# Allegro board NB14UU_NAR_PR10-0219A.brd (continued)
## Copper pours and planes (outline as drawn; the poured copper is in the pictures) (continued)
INT_SPK_L+ on TOP (solid shape): 281.62,53.86 283.39,53.86 283.43,53.83 283.43,53.68 283.37,53.62 281.35,53.62 281.21,53.48 279.46,53.48 279.46,54.11 279.52,54.18 281.3,54.18
INT_SPK_L+ on IN1 (solid shape): 290.89,38.49 290.89,37.28 290.7,37.09 290,37.09 289.75,37.35 289.75,38.49 289.87,38.62 290.76,38.62
INT_SPK_L+ on IN1 (solid shape): 281.24,54.18 281.24,53.6 281.11,53.48 279.46,53.48 278.38,52.4 277.55,52.4 277.24,52.72 277.24,53.16 277.49,53.41 278.38,53.41 279.2,54.24 281.17,54.24
INT_SPK_L- on TOP (solid shape): 289.24,38.55 289.24,37.67 289.05,37.48 288.29,37.48 288.03,37.73 288.03,38.49 288.16,38.62 289.17,38.62
INT_SPK_L- on TOP (solid shape): 283.43,53.42 283.43,53.29 283.38,53.24 281.79,53.24 281.12,52.58 279.54,52.58 279.46,52.65 279.46,53.19 279.52,53.25 281.17,53.25 281.37,53.45 283.4,53.45
INT_SPK_L- on IN1 (solid shape): 289.24,38.43 289.24,37.79 288.48,37.03 288.16,37.03 287.71,37.48 287.71,37.79 288.03,38.11 288.03,38.36 288.29,38.62 289.05,38.62
INT_SPK_L- on IN1 (solid shape): 281.24,53.1 281.24,52.72 281.17,52.65 279.97,52.65 277.93,50.62 277.93,49.92 277.74,49.73 277.05,49.73 276.92,49.86 276.92,50.62 279.52,53.22 281.11,53.22
INT_SPK_R+ on TOP (solid shape): 287.33,38.49 287.33,37.67 287.14,37.48 286.38,37.48 286.19,37.67 286.19,38.49 286.32,38.62 287.21,38.62
INT_SPK_R+ on TOP (solid shape): 283.44,52.62 283.44,52.47 283.4,52.44 282.31,52.44 281.62,51.75 281.62,51.47 280.78,50.63 279.64,50.63 279.46,50.81 279.46,51.38 279.52,51.45 281.02,51.45 281.38,51.81 281.38,52 282.04,52.66 283.39,52.66
INT_SPK_R+ on IN1 (solid shape): 281.24,51.32 281.24,49.92 281.11,49.79 280.35,49.79 280.22,49.92 280.22,50.94 280.09,51.06 280.09,51.32 280.22,51.45 281.11,51.45
INT_SPK_R+ on IN1 (solid shape): 287.33,39.7 287.33,38.3 287.14,38.11 286.38,38.11 286.19,38.3 286.19,39.32 285.68,39.82 285.68,40.14 286,40.46 286.57,40.46
INT_SPK_R- on TOP (solid shape): 285.43,38.49 285.43,37.6 285.3,37.48 284.48,37.48 284.28,37.67 284.28,38.49 284.41,38.62 285.3,38.62
INT_SPK_R- on TOP (solid shape): 283.43,53.01 283.43,52.88 283.37,52.82 281.99,52.82 281.23,52.06 281.23,51.85 281.09,51.71 279.51,51.71 279.46,51.77 279.46,52.33 279.52,52.4 281.16,52.4 281.81,53.05 283.4,53.05
INT_SPK_R- on IN1 (solid shape): 281.24,52.14 281.24,51.95 281.05,51.76 280.22,51.76 279.71,51.25 279.71,49.92 279.59,49.79 278.82,49.79 278.7,49.92 278.7,51.13 279.84,52.27 281.11,52.27
INT_SPK_R- on IN1 (solid shape): 285.43,39 285.43,38.24 285.3,38.11 284.48,38.11 283.65,38.94 283.65,39.57 284.09,40.02 284.41,40.02
INT_SPKR_L+ on TOP (solid shape): 291.27,36.65 291.27,35.06 292.1,34.24 292.1,33.92 291.71,33.54 291.27,33.54 290.13,34.68 290.13,37.03 290.19,37.09 290.83,37.09
INT_SPKR_L+ on TOP (solid shape): 294.32,32.08 294.32,29.86 294.13,29.66 293.56,29.66 293.43,29.79 293.43,31.51 293.17,31.76 293.17,32.08 293.43,32.33 294.06,32.33
INT_SPKR_L+ on BOTTOM (solid shape): 294.25,30.55 294.25,27.38 294.06,27.19 293.49,27.19 293.37,27.32 293.37,30.62 293.56,30.81 294,30.81
INT_SPKR_L- on TOP (solid shape): 289.3,36.9 289.3,34.49 289.11,34.3 289.11,33.03 288.86,32.78 288.22,32.78 288.09,32.9 288.09,36.65 288.54,37.09 289.11,37.09
INT_SPKR_L- on TOP (solid shape): 292.86,31.32 292.86,29.79 292.73,29.66 292.29,29.66 291.84,30.11 291.84,30.49 291.52,30.81 291.14,30.81 291.02,30.93 291.02,31.51 291.33,31.82 292.35,31.82
INT_SPKR_L- on BOTTOM (solid shape): 292.98,30.55 292.98,27.38 292.79,27.19 292.35,27.19 292.16,27.38 292.16,30.55 292.41,30.81 292.73,30.81
INT_SPKR_R+ on TOP (solid shape): 287.46,32.08 287.46,31.25 287.78,30.93 287.78,30.62 287.59,30.43 286.91,30.43 286.33,31.01 286.33,32.03 286.57,32.27 287.27,32.27
INT_SPKR_R+ on TOP (solid shape): 287.4,36.8 287.4,34.08 287.52,33.97 287.52,33.38 287.47,33.34 286.44,33.34 286.44,33.34 286.37,33.55 286.23,33.73 286.23,36.97 286.36,37.1 287.11,37.1
INT_SPKR_R+ on BOTTOM (solid shape): 287.29,31.31 287.59,31.31 287.82,31.24 288.04,31.32 290.76,31.32 291.71,30.36 291.71,27.38 291.52,27.19 291.08,27.19 290.89,27.38 290.89,29.41 290.13,30.17 288.66,30.17 288.41,30.28 288.16,30.17 287.33,30.17 286.7,30.81 286.7,31.19 286.82,31.32 287.29,31.32
INT_SPKR_R- on TOP (solid shape): 285.37,36.89 285.37,33.72 285.28,33.62 285.22,33.49 285.12,33.4 284.26,33.4 284.19,33.47 284.19,36.98 284.3,37.09 285.17,37.09
INT_SPKR_R- on TOP (solid shape): 285.17,31.95 285.17,31.44 285.94,30.67 285.94,30.27 285.77,30.1 284.99,30.1 284.16,30.93 284.16,31.95 284.41,32.2 284.92,32.2
INT_SPKR_R- on BOTTOM (solid shape): 287.47,29.09 288.16,29.09 288.41,28.98 288.67,29.09 290.23,29.09 290.47,28.85 290.47,27.43 290.22,27.18 289.76,27.18 289.62,27.32 289.62,27.89 289.43,28.08 286.76,28.08 284.67,30.17 284.67,30.57 285.17,31.08 285.48,31.08
LDO_3V on BOTTOM (solid shape): 207.77,37.22 207.7,37.16 206.31,37.16 206.18,37.03 206.18,34.62 206.05,34.49 205.35,34.49 205.23,34.62 205.23,35.19 205.48,35.44 205.48,37.72 207.77,37.72
LG1_CHG on BOTTOM (solid shape): 86.09,44.63 86.75,44.63 87.03,44.35 87.03,44.09 86.88,43.94 85.74,43.94 85.63,44.04 85.63,44.8 85.68,44.85 85.86,44.85
LG1_CHG on BOTTOM (solid shape): 105.02,34.55 105.02,32.59 104.77,32.33 103.88,32.33 103.69,32.52 103.69,33.35 103.25,33.79 103.25,34.55 103.31,34.62 104.96,34.62
LG1_CHG on IN1 (solid shape): 104.9,33.03 104.9,32.52 104.71,32.33 102.8,32.33 102.55,32.59 102.55,33.03 102.87,33.35 104.58,33.35
LG1_CHG on IN1: 86.43,43.86 86.12,43.86 85.93,44.05 85.93,44.44 86.12,44.63 87.07,44.63 88.21,43.48 88.21,42.82 88.17,42.78 87.21,42.78 87.16,42.84 87.16,43.14
LG2_CHG on BOTTOM (solid shape): 122.23,40.14 122.23,39.57 122.11,39.44 120.52,39.44 120.2,39.13 119.95,39.13 119.76,39.32 119.76,40.08 120.01,40.33 122.04,40.33
LG2_CHG on BOTTOM (solid shape): 87.98,45.16 87.98,44.85 87.88,44.75 87.58,44.75 86.97,45.36 85.98,45.36 85.93,45.41 85.93,45.51 85.98,45.57 86.84,45.57 86.89,45.62 87.53,45.62
LG2_CHG on IN1 (solid shape): 120.33,40.14 120.33,39.25 120.2,39.13 118.8,39.13 118.61,39.32 118.61,39.95 118.93,40.27 120.2,40.27
LG2_CHG on IN1: 87.01,45.35 87.01,45.58 87.13,45.71 87.7,45.71 87.89,45.51 88.64,45.51 89.22,44.94 89.22,44.72 88.61,44.11 88.47,44.11 87.83,44.74 87.61,44.74
LG_SA on TOP (solid shape): 176.94,135.19 176.94,134.44 177.11,134.27 177.11,133.78 177.05,133.72 176.16,133.72 176.11,133.77 176.11,135.2 176.16,135.25 176.89,135.25
LG_SA on TOP (solid shape): 185.87,133.79 185.87,133.32 185.69,133.13 184.25,133.13 184.02,132.9 183.07,132.9 182.97,132.99 182.97,133.71 183.03,133.77 183.95,133.77 184.06,133.88 185.78,133.88
LG_SA on IN3 (solid shape): 176.96,135.08 176.96,134.11 177.19,133.89 182.63,133.89 182.77,133.75 185.56,133.75 185.73,133.59 185.73,131.87 185.64,131.79 183.53,131.79 182.49,132.83 176.44,132.83 176.1,133.17 176.1,135.11 176.18,135.19 176.85,135.19
LX1_CHG on BOTTOM (solid shape): 99.5,35.89 99.5,35.25 99.44,35.19 98.93,35.19 98.74,35 98.36,35 98.23,35.13 98.23,36.01 98.36,36.14 99.25,36.14
LX1_CHG on BOTTOM (solid shape): 110.36,39.82 110.36,33.98 109.98,33.6 106.87,33.6 105.21,35.25 104.39,35.25 104.39,38.43 105.66,39.7 105.66,40.46 105.72,40.52 109.66,40.52
LX1_CHG on BOTTOM (solid shape): 85.44,44.83 85.44,44.04 86.5,42.99 86.5,41.64 85.61,41.64 85.55,41.7 85.55,43.04 85.23,43.36 85.23,44.82 85.27,44.85 85.42,44.85
LX1_CHG on IN3 (solid shape): 105.98,35.95 105.98,35.13 105.79,34.94 105.47,34.94 105.09,34.55 104.77,34.55 104.33,35 104.33,35.25 105.15,36.08 105.85,36.08
LX1_CHG on IN3 (solid shape): 99.75,35.06 99.75,34.74 99.63,34.62 98.8,34.62 98.29,35.13 97.34,35.13 97.15,35.32 97.15,36.01 97.28,36.14 98.67,36.14
LX1_CHG on IN3: 85.35,43.23 85.35,43.61 85.48,43.74 87.39,43.74 87.39,42.72 85.86,42.72
LX1_IA on TOP (solid shape): 118.61,106.31 118.61,105.1 118.36,104.85 116.96,104.85 116.9,104.91 116.9,106.56 116.96,106.63 118.3,106.63
LX1_IA on BOTTOM (solid shape): 115.76,108.09 115.76,107.07 116.58,107.07 116.58,108.02 116.77,108.21 118.74,108.21 119.25,107.71 119.25,102.5 119.06,102.31 118.23,102.31 118.17,102.37 118.17,103.52 117.91,103.77 114.17,103.77 113.79,104.15 113.79,107.9 114.17,108.28 115.57,108.28
LX2_CHG on BOTTOM (solid shape): 127.19,39.06 127.19,38.17 127.06,38.05 125.98,38.05 125.92,38.11 125.92,38.75 125.98,38.81 126.36,38.81 126.74,39.19 127.06,39.19
LX2_CHG on BOTTOM (solid shape): 119.44,42.75 119.44,39.19 119.76,38.87 121.03,38.87 121.09,38.81 121.09,34.49 120.58,33.98 115.25,33.98 114.75,34.49 114.75,41.86 115.88,43 119.18,43
LX2_CHG on BOTTOM (solid shape): 89.48,46.26 89.48,45.45 89.16,45.13 88.26,45.13 87.65,45.74 85.98,45.74 85.93,45.79 85.93,45.92 85.98,45.97 88.16,45.97 88.28,46.09 88.72,46.09 89.03,46.39 89.35,46.39
LX2_CHG on IN3 (solid shape): 90.67,46.63 90.67,45.62 90.28,45.23 89.07,45.23 88.94,45.36 88.94,46.5 89.15,46.71 90.6,46.71
LX2_CHG on IN3 (solid shape): 126.74,40.52 126.74,39.51 127.25,39 127.25,38.24 127.06,38.05 126.3,38.05 125.73,38.62 125.73,40.46 126.11,40.84 126.42,40.84
LX2_CHG on IN3 (solid shape): 121.47,39.38 121.47,38.94 120.14,37.6 118.87,37.6 118.61,37.86 118.61,38.49 118.87,38.75 120.07,38.75 120.45,39.13 120.45,39.38 120.65,39.57 121.28,39.57
LX2_IA on TOP (solid shape): 101.72,111.71 101.53,111.52 100.26,111.52 100.07,111.71 100.07,113.29 101.72,113.29
LX2_IA on BOTTOM (solid shape): 102.48,115.96 102.48,114.5 102.29,114.31 101.28,114.31 101.28,113.48 102.23,113.48 102.36,113.36 102.36,112.62 105.98,109 105.98,107.82 105.42,107.26 104.26,107.26 104.26,108.47 104.01,108.72 99.74,108.72 98.51,109.95 98.51,113.93 98.54,114.14 98.51,114.35 98.51,115.35 99.31,116.15 102.29,116.15
LX_1.05VALWP on TOP (solid shape): 234.41,129.88 234.41,128.64 234.27,128.5 233.73,128.5 233.61,128.62 233.61,129.65 233.55,129.72 233.55,129.91 233.61,129.97 234.31,129.97
LX_1.05VALWP on TOP (solid shape): 229.22,133.24 229.22,130.8 229.59,130.43 231.21,130.43 231.33,130.31 231.33,129.8 231.01,129.49 231.01,128.66 230.5,128.15 230.5,127.2 230.37,127.07 227.9,127.07 226.65,128.32 226.65,133.46 226.69,133.5 228.96,133.5
LX_1.05VALWP on BOTTOM (solid shape): 234.12,129.45 234.12,128.63 234,128.51 230.52,128.51 229.9,127.9 228.66,127.9 228.66,129.55 228.69,129.58 233.98,129.58
LX_1.8VALW on BOTTOM (solid shape): 198.5,114.37 198.69,114.18 201.36,114.18 201.8,113.75 201.8,113.23 201.61,113.04 197.92,113.04 197.86,113.1 197.86,115.33 198.5,115.33
LX_1V_PRIM_CORE on TOP (solid shape): 207.83,131.14 207.83,130.5 207.77,130.44 206.97,130.44 206.61,130.07 206.61,129.28 206.08,128.75 204.89,128.75 204.87,128.72 203.51,128.72 203.39,128.85 203.39,130.12 204.47,131.2 207.77,131.2
LX_1V_PRIM_CORE on BOTTOM (solid shape): 205.16,131.01 205.16,130.12 205.04,129.99 203.88,129.99 203.75,130.12 203.75,131.02 203.86,131.13 203.95,131.13 203.96,131.14 205.04,131.14
LX_1VS_VCCIO on TOP: 106.83,75.69 106.83,75.08 106.9,75.01 110.55,75.01 110.93,75.38 110.93,76.78 110.8,76.91 110.17,76.91 109.79,77.29 109.79,77.8 109.66,77.92 108.14,77.92 107.88,77.67 107.88,75.89 107.75,75.76 106.9,75.76
LX_3V on TOP (solid shape): 206.19,35.28 206.19,32.09 205.95,31.85 204.87,31.85 204.65,32.07 204.65,35.29 204.79,35.43 206.04,35.43
LX_3V on BOTTOM (solid shape): 203.03,33.34 203.03,33.21 202.81,32.99 202.81,32.54 202.32,32.04 202.01,32.04 201.93,32.13 201.93,33.11 202.22,33.4 202.97,33.4
LX_3V on BOTTOM (solid shape): 210.37,34.36 210.37,31.19 209.61,30.43 205.54,30.43 205.42,30.55 205.42,33.06 205.27,33.21 205.27,33.79 205.33,33.86 206.94,33.86 207.26,34.17 207.26,34.81 207.32,34.87 209.86,34.87
LX_3V on IN2 (solid shape): 202.75,32.9 205.48,32.9 205.61,33.03 205.93,33.03 206.05,32.9 206.05,32.08 205.86,31.89 202.12,31.89 201.93,32.08 201.93,32.65 202.31,33.03 202.62,33.03
LX_5V on BOTTOM (solid shape): 87.69,77.8 87.69,76.53 85.78,74.62 81.82,74.62 80.26,73.06 79.7,73.06 79.63,73.14 79.63,77.23 80.32,77.92 87.56,77.92
LX_5V on IN3 (solid shape): 81.47,74.75 81.47,74.5 81.15,74.18 81.15,69.73 80.96,69.54 80.51,69.54 80.32,69.73 80.32,74.75 80.45,74.88 81.34,74.88
LX_5V on BOTTOM: 80.15,70.85 80.79,70.85 80.96,70.69 80.96,69.67 80.83,69.54 80.32,69.54 80.08,69.79 80.08,70.78
LX_DDR on TOP (solid shape): 91.95,63.4 91.95,62.06 91.74,61.86 89.85,61.86 89.6,62.11 89.6,63.45 89.73,63.57 91.78,63.57
LX_DDR on BOTTOM (solid shape): 92.2,59.07 91.18,58.05 87.37,58.05 87.18,58.24 87.18,60.51 87.03,60.67 85.72,60.67 85.61,60.78 85.61,61.49 85.71,61.59 87.17,61.59 87.24,61.67 88.32,61.67 90.86,64.21 90.86,65.86 92.2,65.86
LX_GT on TOP (solid shape): 111.76,86.37 111.76,84.85 111.56,84.66 110.23,84.66 109.98,84.91 109.98,86.37 110.04,86.43 111.69,86.43
LX_GT on BOTTOM (solid shape): 113.09,89.8 113.09,88.34 112.96,88.21 111.88,88.21 111.88,87.32 112.9,87.32 113.03,87.2 113.03,85.1 112.39,84.47 107.69,84.47 107.12,85.04 107.12,85.99 108.39,85.99 108.58,86.18 108.58,89.93 108.71,90.05 112.83,90.05
LX_SA on TOP (solid shape): 176.04,133.55 179.19,133.55 179.76,134.12 179.76,134.19 179.83,134.25 181.35,134.25 181.8,133.8 181.8,132.98 181.73,132.92 181.61,132.92 180.97,133.55 179.89,133.55 179.13,132.79 179.13,132.53 179,132.41 176.46,132.41 176.21,132.15 176.21,131.49 175.99,131.26 174.57,131.26 174.08,130.77 173.09,130.77 172.91,130.96 172.91,132.28 173.03,132.41 173.99,132.41 173.99,133.23 173.03,133.23 172.98,133.29 172.98,134.26 173.11,134.39 175.2,134.39
LX_SA on BOTTOM (solid shape): 175.28,132.78 175.28,131.09 175.08,130.88 173.14,130.88 173,131.03 173,132.52 173.46,132.99 175.07,132.99
RING2 on TOP (solid shape): 290.83,52.53 290.83,52.14 290.7,52.01 289.35,52.01 288.98,52.38 288.84,52.38 288.81,52.41 287.73,52.41 287.66,52.47 287.66,52.6 287.73,52.66 290.7,52.66
RING2 on BOTTOM (solid shape): 300.51,34.55 300.51,33.94 300.17,33.6 299.65,33.6 299.53,33.59 299.42,33.56 299.41,33.56 297.28,33.56 296.89,33.95 296.89,34.72 296.94,34.77 300.29,34.77
RING2 on IN1 (solid shape): 292.03,52.21 292.03,51.45 291.78,51.19 289.75,51.19 289.17,51.76 289.17,52.4 289.3,52.52 291.71,52.52
RING2 on IN1 (solid shape): 300.53,35.52 300.53,33.72 300.4,33.59 299.41,33.59 299.19,33.81 299.19,35.43 299.55,35.79 300.27,35.79
RING2_R on BOTTOM (solid shape): 303.51,37.26 303.51,35.39 303.2,35.08 302.43,35.08 302.27,35.25 302.27,35.92 302.08,36.11 301.84,36.11 300.79,35.05 297.05,35.05 296.89,35.21 296.89,36.39 296.97,36.47 300.19,36.47 301.27,37.55 303.22,37.55
SLEEVE on TOP (solid shape): 290.83,53.29 290.83,52.97 290.7,52.84 289.11,52.84 289.11,52.84 287.7,52.84 287.7,53.04 288.8,53.04 289.17,53.41 290.7,53.41
SLEEVE on BOTTOM (solid shape): 296.8,38.68 296.8,38.2 297.01,37.99 297.01,37.66 296.8,37.45 296.8,36.66 296.61,36.48 295.97,36.48 295.91,36.54 295.91,38.78 295.94,38.81 296.66,38.81
SLEEVE on IN3 (solid shape): 292.1,53.67 292.1,52.91 291.9,52.72 289.43,52.72 289.17,52.97 289.17,53.73 289.43,53.99 291.78,53.99
SLEEVE on IN3 (solid shape): 297.05,39.19 297.05,37.28 296.92,37.16 296.1,37.16 295.78,37.48 295.78,39.19 296.03,39.44 296.79,39.44
SLEEVE_R on BOTTOM (solid shape): 301.3,39.89 303.33,39.89 303.53,39.7 303.53,38.62 303.07,38.16 301.39,38.16 301.01,38.55 299.09,38.55 298.56,39.07 296.01,39.07 295.91,39.18 295.91,40.23 296.07,40.4 300.79,40.4
SLEEVE_R on IN3 (solid shape): 303.46,39.72 303.46,39.14 303.26,38.94 302.42,38.94 302.24,39.11 302.24,39.72 302.4,39.88 303.31,39.88
SNUB1_IA on TOP (solid shape): 115.25,106.56 115.25,104.91 113.6,104.91 113.22,105.29 113.22,106.44 113.41,106.63 115.18,106.63
SNUB2_IA on TOP (solid shape): 101.72,109.61 99.28,109.61 99.12,109.77 99.12,110.5 99.25,110.63 101.72,110.63
SNUB_1.05VALWP on BOTTOM (solid shape): 227.45,128.09 227.26,127.9 225.99,127.9 225.99,130.19 226.63,130.82 227.45,130.82
SNUB_1.8VALW on BOTTOM (solid shape): 200.74,115.24 200.74,114.58 200.58,114.42 199.17,114.42 199.13,114.46 199.13,115.35 199.17,115.39 200.59,115.39
SNUB_1VS_VCCIO on TOP: 108.77,79.32 110.68,79.32 110.8,79.19 110.8,78.69 110.55,78.43 108.77,78.43 108.64,78.56 108.64,79.19
SNUB_3V on TOP (solid shape): 203.45,33.67 202.43,33.67 202.43,34.17 202.18,34.43 201.65,34.43 201.48,34.59 201.48,35.32 203.45,35.32
SNUB_5V on BOTTOM (solid shape): 87.72,81.2 87.72,79.35 87.56,79.19 86.04,79.19 85.78,79.45 85.78,81.48 85.91,81.61 87.31,81.61
SNUB_DDR on TOP (solid shape): 91.18,67.19 91.18,66.43 91.37,66.24 91.4,66.24 91.41,66.21 91.44,66.17 91.47,66.13 91.47,65.11 91.37,65.01 89.84,65.01 89.68,65.18 89.68,66.35 90.58,67.26 91.12,67.26
SNUB_GT on TOP (solid shape): 111.76,89.86 111.76,88.08 111.69,88.02 110.04,88.02 109.98,88.08 109.98,89.04 110.49,89.55 110.49,90.31 110.55,90.37 111.25,90.37
UG1_CHG on BOTTOM (solid shape): 85.09,44.78 85.09,42.71 84.97,42.59 84.73,42.59 84.6,42.72 84.6,43.51 84.83,43.74 84.83,44.8 84.88,44.85 85.01,44.85
UG1_CHG on BOTTOM (solid shape): 98.74,34.68 99.44,34.68 99.5,34.62 99.5,33.98 99.44,33.92 98.86,33.92 98.61,33.67 98.17,33.67 97.98,33.86 97.98,34.68 98.1,34.81 98.61,34.81
UG1_CHG on IN3 (solid shape): 98.48,34.62 98.48,33.79 98.36,33.67 97.47,33.67 97.21,33.92 97.21,34.68 97.34,34.81 98.29,34.81
UG1_CHG on IN3: 84.34,42.15 84.34,43.55 84.47,43.67 85.04,43.67 85.1,43.61 85.1,43.17 85.74,42.53 85.99,42.53 85.99,41.51 84.97,41.51
UG2_CHG on BOTTOM (solid shape): 127.57,40.4 127.57,39.63 127.38,39.44 125.92,39.44 125.92,40.08 125.98,40.14 126.61,40.14 127.06,40.59 127.38,40.59
UG2_CHG on BOTTOM (solid shape): 88.08,46.61 88.08,46.2 87.98,46.1 86.92,46.1 86.87,46.15 85.98,46.15 85.93,46.2 85.93,46.33 85.98,46.38 87.02,46.38 87.2,46.56 87.6,46.56 87.75,46.71 87.98,46.71
UG2_CHG on IN3 (solid shape): 88.91,47.55 88.91,46.98 87.96,46.02 87.2,46.02 87.01,46.21 87.01,46.47 88.15,47.61 88.85,47.61
UG2_CHG on IN3 (solid shape): 127.76,41.35 127.76,39.63 127.57,39.44 127.19,39.44 126.93,39.7 126.93,40.65 126.55,41.03 126.55,41.48 126.8,41.73 127.38,41.73
UG_SA on TOP (solid shape): 177.13,131.39 177.13,130.48 177,130.36 176.09,130.36 176.01,130.43 176.01,130.75 176.74,131.48 177.04,131.48
UG_SA on TOP (solid shape): 181.47,132.14 181.47,131.67 181.58,131.57 181.72,131.57 181.77,131.52 181.77,130.81 181.66,130.7 180.99,130.7 180.71,130.98 180.71,131.97 180.98,132.24 181.37,132.24
UG_SA on IN1 (solid shape): 181.38,132.13 181.38,131.19 181.27,131.08 177.72,131.08 177,130.36 176.09,130.36 176.01,130.43 176.01,131.07 177.23,132.28 181.23,132.28
VOUT_1.2V_RUN on TOP: 285.87,97.14 286.23,96.78 288.38,96.78 288.4,96.76 288.4,96.22 288.18,96 288.18,95.18 288.17,95.17 287.63,95.17 287.62,95.15 287.62,94.71 287.63,94.71 288.17,94.71 288.18,94.7 288.18,94.36 288.05,94.23 285.96,94.23 285.96,94.24 285.46,94.24 285.19,94.51 285.19,96.38 284.82,96.75 284.82,97.01 284.95,97.14
VOUT_2.5V_MEM on TOP (solid shape): 242.23,58.43 242.23,56.59 242.68,56.13 244.11,56.13 244.17,56.07 244.17,55.61 244.14,55.59 242.34,55.59 242.15,55.78 241.64,55.78 241.64,56.35 241.13,56.35 241.13,55.78 240.21,55.78 240,56 240,58.11 240.18,58.29 241.58,58.29 241.85,58.56 242.1,58.56
N43975 on TOP: 252.05,33.98 253.15,33.98 253.29,33.84 253.29,32.21 253.02,31.94 252.3,31.94 251.97,32.27 251.97,33.91
N16783222 on BOTTOM: 76.13,74.37 78.8,74.37 78.98,74.18 78.98,73.14 78.91,73.06 78.33,73.06 78.16,73.23 77.15,73.23 76.77,73.61 76.13,73.61 76,73.73 76,74.24
N17370862 on BOTTOM (solid shape): 77.91,113.36 77.91,112.85 77.66,112.6 77.66,109.8 77.53,109.67 77.02,109.67 76.89,109.8 76.89,112.72 76.77,112.85 75.62,112.85 75.31,112.53 75.31,111.77 74.99,111.45 74.48,111.45 74.1,111.83 74.1,113.23 74.48,113.61 77.66,113.61
N17371029 on BOTTOM (solid shape): 77.02,119.96 77.4,119.96 77.57,119.8 77.57,119.37 77.44,119.24 74.84,119.24 74.73,119.34 74.73,120.05 75.28,120.6 76.39,120.6
N24654285 on TOP: 283.35,82.45 282.98,82.81 282.61,82.81 282.55,82.88 282.55,83.03 282.66,83.14 282.84,83.14 283.77,84.08 285.43,84.08 285.49,84.02 285.49,82.61 285.33,82.45
N26619306 on BOTTOM (solid shape): 101.15,104.53 101.15,103.71 100.58,103.13 100.58,102.18 100.44,102.05 99.87,102.05 99.8,102.12 99.8,103.36 99.91,103.46 100.4,103.46 100.77,103.83 100.77,104.53 100.83,104.59 101.09,104.59
N26619381 on BOTTOM (solid shape): 103.31,90.33 103.31,89.86 103.7,89.47 104.39,89.47 104.46,89.41 104.46,89.16 104.39,89.09 103.57,89.09 103,89.66 102.06,89.66 101.93,89.79 101.93,90.43 101.96,90.45 103.19,90.45
N27174658 on TOP (solid shape): 74.2,37.59 74.2,36.99 74.5,36.69 75.03,36.69 75.34,36.37 75.34,35.3 75.25,35.21 72.11,35.21 71.98,35.34 71.98,35.73 72.46,36.21 72.46,36.75 72.71,37 72.71,37.61 72.83,37.73 74.06,37.73
N27175412 on TOP (solid shape): 67.36,113.85 67.36,113.18 67.18,112.99 64.72,112.99 64.65,113.06 64.65,113.99 64.73,114.07 67.14,114.07
N27540667 on TOP (solid shape): 69.04,113.84 69.04,111.63 68.96,111.55 67.6,111.55 67.53,111.63 67.53,113.83 67.73,114.03 68.84,114.03
N27698752 on TOP (solid shape): 119.43,133.82 120.58,133.82 120.88,133.52 120.88,132.6 120.67,132.4 117.91,132.4 117.85,132.46 117.85,134.59 117.89,134.63 118.63,134.63
N49223737 on BOTTOM (solid shape): 115.13,99.58 115.13,98.76 114.56,98.18 114.56,97.15 114.49,97.09 113.82,97.09 113.79,97.12 113.79,98.38 113.98,98.56 114.43,98.56 114.75,98.88 114.75,99.58 114.81,99.64 115.06,99.64

Small or netless copper shapes (teardrops, artwork), in the pictures only: 205 on TOP, 153 on BOTTOM, 2 on IN2

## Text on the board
Ref Des/Silkscreen Bottom: H11 | H12 | H7 | H8 | H15 | COPYRIGHT 2019 | ALL RIGHT RESERVED | REV:A00 | PWB P/N:HC1WK
User.Comments: CR_UNNAMED_1 | LA-G891P | 2020-02-18 | 2019-02-18 | EDC41 | Minjia
Ref Des/Silkscreen Top: H17
User.11: LAYER | NO. | L1 | L2 | L3 | L4 | L5 | L6 | L7 | L8 | LA-G891P | GND1 | GND2 | TOP | IN1 | IN2 | VCC | IN3 | BOT | DUMMY COPPER | LS-G891P | Secret Level | Issued | Decipherment date | BOARD Thickness(mm) | PROJECT | DRAW BY | BOARD NO. | Date | COMPAL ELECTRONICS. INC. | Secret data | REV: | 226.9 | 228.9 | 214.9 | -3 | -5 | 209.9 | 211.4 | 134 | 185.75 | X:30.58 | Y:149.18 | 216.4 | 217.9 | 1 | 155.9 | 148.9 | 115.5 | 121.3 | X:68.29 | Y:160.68 | X:72.8 | Y:125.99 | Print white paint on BOT silkscreen | Print white paint on TOP silkscreen | 0 | 223.9 | X:252.25 | Y:97.91 | X:256.76 | Y:63.22 | 108.4 | 102.6 | 68 | 75 | 222.9 | REV:0.3 | (TOP) | 7.5 | X:294.47 | Y:74.72 | 6 | 38.15 | 89.9 | 14 | 12.5 | 9 | ZORA-ZHU | 2018-12-17 | 2019-12-17 | 1.2 | EDC41 | 10% | 0.3 | -4 | 10.7 | 12.05 | 10.05 | 11.05 | 13.55 | 18.55 | 20.05 | 43.05 | 45.05 | 42 | 44 | 53.05 | 57.05 | 72 | 78 | 106.05 | 116.03 | 120 | 150.05 | 162.53 | 175 | 205.05 | 209.03 | 219 | 247.05 | 253.05 | 268 | 272 | 281.05 | 280 | 283.05 | 282 | 305 | 306.5 | 311.5 | 314 | 314.35 | 315 | 313 | 324.05 | 325.05 | 329.05 | R5X4 | R3X4 | Tooling Hole:2.7mm(+/-1.5mil) x4 | Tooling Hole:2mm x3 | Barcode area:8X8 on top side onlyX2 | Notes: | 1.To Use 2mm(min) router | for breakaway | 2.Refer to detail 2M,4M,8M, | 10M for TAB spec. | REV:0.3(TOP) | 0.127mm | F | 333.05 | 233.9
User.40: trace Width | 4.8 | 4.2 | 3.9 | 4 | 4/3.5 | 3.5/3.6 | 3.8/3.5 | 3.5/9.6 | 3.5/7.1 | 3.8 | Width/Space | SB_1_2mm-8L(3mil core)(1080 1086)_180425.pdf | 45 ohm | L4/L7 | L2/L4 | Ref | L7 | L2 | 50 ohm | 85 ohm | L5/L7
User.42: FIGURE | SIZE | 8.0 | 22.0 | 28.0 | 35.0 | 102.0 | 118.0 | 126.0 | 130.0 | 150.0 | 157.0 | 30.0 | 31.0 | 43.0 | 63.0 | 71.0 | 83.0 | 197.0 | 47.0x20.0 | 49.0x28.0 | 55.0x24.0 | 55.0x39.0 | 71.0x28.0 | 75.0x24.0 | 79.0x24.0 | 79.0x28.0 | 87.0x39.0 | 33.0x28.0 | 122.0x83.0 | DRILL CHART: TOP to BOTTOM | ALL UNITS ARE IN MILS | TOLERANCE | +3.0/-3.0 | +2.0/-2.0 | PLATED | NON-PLATED | QTY | 6594 | 19 | 27 | 10 | 4 | 1 | 2 | 3 | 9 | 5 | 7 | 12
User.43: stack-up setting ok
